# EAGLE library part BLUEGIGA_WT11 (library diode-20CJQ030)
BlueGiga's WT11 Bluetooth Module (2.0+EDR) Description: BlueCore4 is a single chip Bluetooth solution which implements the Bluetooth radio transceiver and also an on chip microcontroller. BlueCore4 implements Bluetooth® 2.0+EDR (Enhanced Data Rate) and it can deliver data rates up to 3 Mbps. The microcontroller (MCU) on BlueCore04 acts as interrupt controller and event timer run the Bluetooth software stack and control the radio and host interfaces. A 16-bit reduced instruction set computer (RISC) microcontroller is used for low power consumption and efficient use of memory. BlueCore04 has 48Kbytes of on-chip RAM is provided to support the RISC MCU and is shared between the ring buffers used to hold voice/data for each active connection and the general purpose memory required by the Bluetooth stack. Featrures: Fully Qualified Bluetooth system v2.0 + EDR, CE and FCC Class 1, range up to 300 meters Integrated chip antenna or UFL connector Industrial temperature range from -40oC to +85oC Enhanced Data Rate (EDR) compliant with v2.0.E.2 of specification for both 2Mbps and 3Mbps modulation modes RoHS Compliant Full Speed Bluetooth Operation with Full Piconet Scatternet Support USB version 2.0 compatible UART with bypass mode Support for 802.11 Coexistence 8Mbits of Flash Memory Applications: Hand held terminals Industrial devices Point-of-Sale systems PCs Personal Digital Assistants (PDAs) Computer Accessories Access Points Please send any comments to: messi@users.sourceforge.net
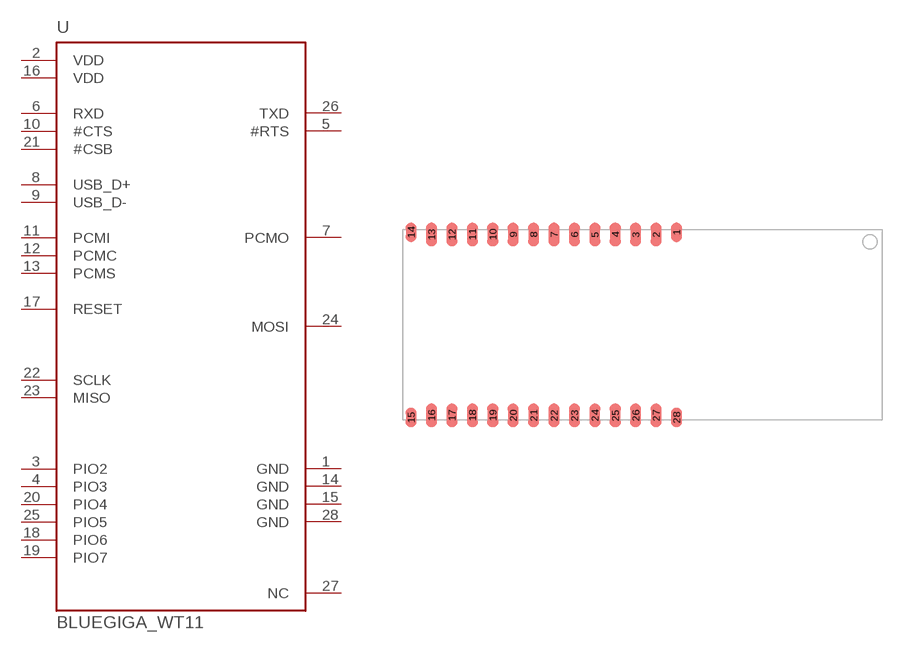
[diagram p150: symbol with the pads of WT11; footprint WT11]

Designator prefix U

## BLUEGIGA_WT11  [WT11]
1  GND  pwr
2  VDD  pwr
3  PIO2
4  PIO3
5  #RTS  out
6  RXD  in
7  PCMO  out
8  USB_D+  sup
9  USB_D-  sup
10  #CTS  in
11  PCMI  in
12  PCMC
13  PCMS
14  GND  pwr
15  GND  pwr
16  VDD  pwr
17  RESET  in
18  PIO6
19  PIO7
20  PIO4
21  #CSB  in
22  SCLK
23  MISO  in
24  MOSI  out
25  PIO5
26  TXD  out
27  NC  nc
28  GND  pwr

## Footprint WT11 (pad centres in mm)
Footprint for the WT11 Bluetooth module from BlueGiga
smd 0.8 x 1.4: 1 2.3,6.8; 14 -17.2,6.8; 15 -17.2,-6.8; 28 2.3,-6.8
smd 0.8 x 1.7: 2 0.8,6.65; 3 -0.7,6.65; 4 -2.2,6.65; 5 -3.7,6.65; 6 -5.2,6.65; 7 -6.7,6.65; 8 -8.2,6.65; 9 -9.7,6.65; 10 -11.2,6.65; 11 -12.7,6.65; 12 -14.2,6.65; 13 -15.7,6.65; 16 -15.7,-6.65; 17 -14.2,-6.65; 18 -12.7,-6.65; 19 -11.2,-6.65; 20 -9.7,-6.65; 21 -8.2,-6.65; 22 -6.7,-6.65; 23 -5.2,-6.65; 24 -3.7,-6.65; 25 -2.2,-6.65; 26 -0.7,-6.65; 27 0.8,-6.65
